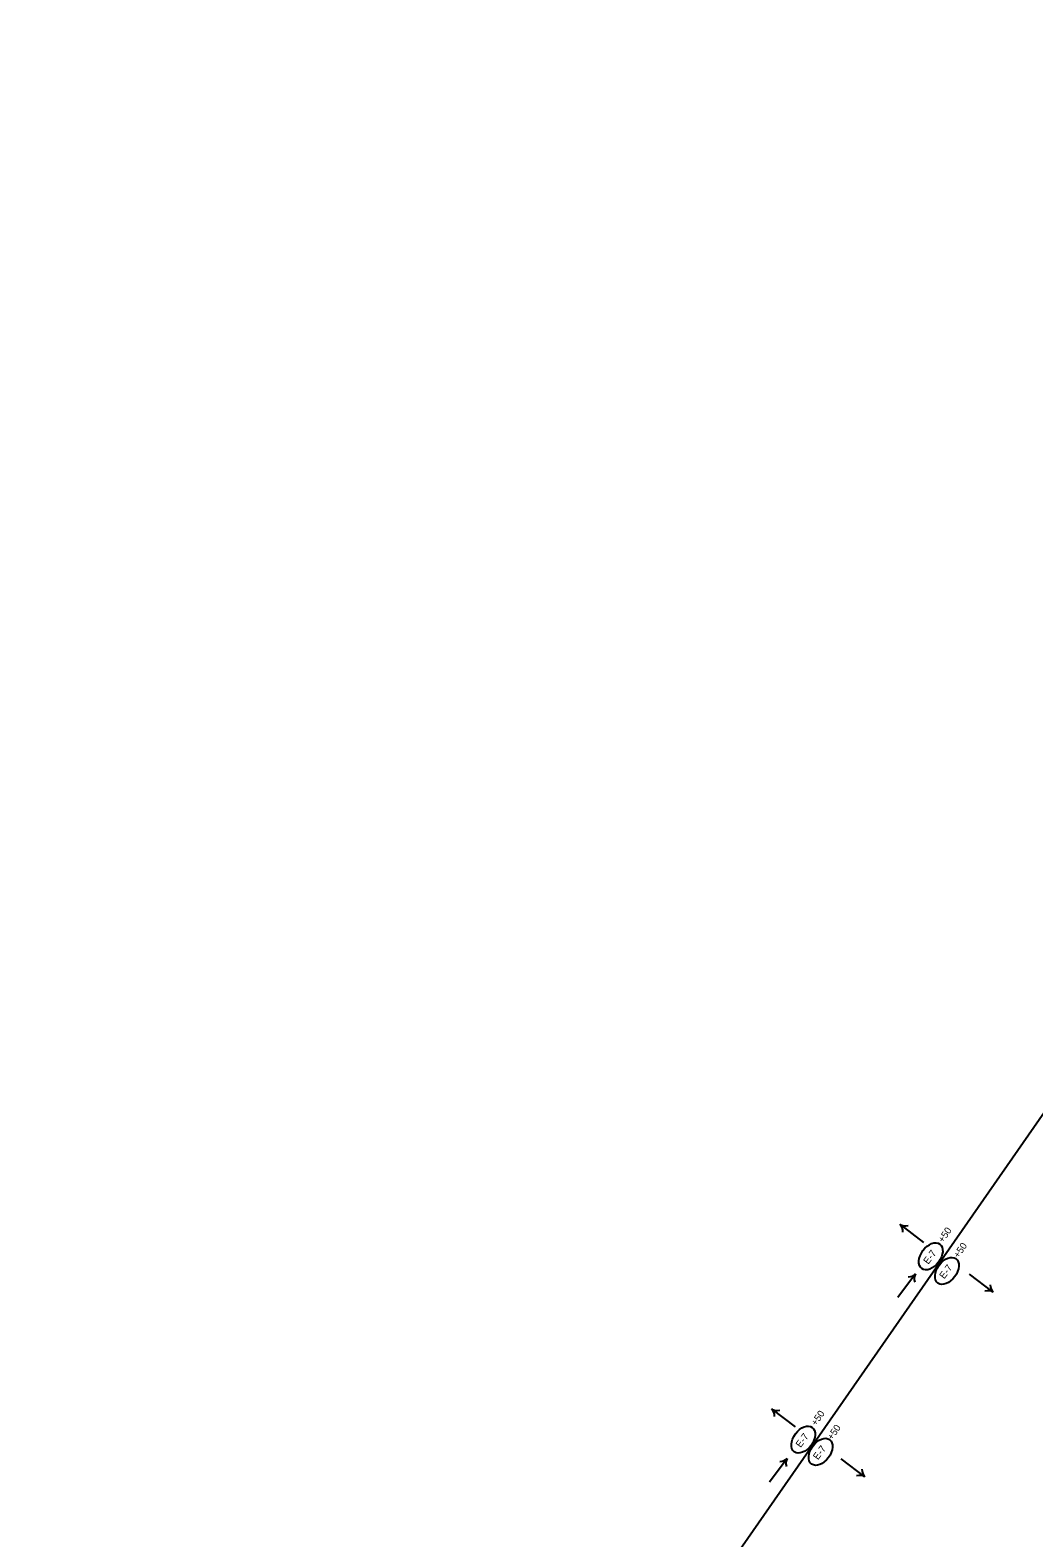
# Model space of a CAD drawing. Extents: x 669236 to 673912, y 735758 to 754788.
# Drawn here: x 671572 to 672475, y 746819 to 748174 of the extents above; entities that cross this region are included whole.
import ezdxf

# ---------------------------------------------------------------- set-up
doc = ezdxf.new("R2010")
doc.units = 0
for name, color, linetype in [('Default', 7, 'Continuous'), ('R_Erosion_2', 7, 'Continuous'), ('R_Flow Arrows', 7, 'Continuous')]:
    doc.layers.add(name, color=color, linetype=linetype)

msp = doc.modelspace()

# ---------------------------------------------------------------- linework, layer by layer
at = {"layer": 'Default'}
msp.add_line((671572, 745891.2), (673440.9, 748577.2), dxfattribs=at)
at = {"layer": 'R_Erosion_2'}
for centre in [(672381.9, 747072.1), (672396.4, 747059), (672267.2, 746907.3), (672282.8, 746896.3)]:
    msp.add_ellipse(centre, major_axis=(8.1, 11), ratio=0.638788, dxfattribs=at)
at = {"layer": 'R_Flow Arrows'}
for p, q in [((672354.3, 747100.7), (672375.4, 747084.6)), ((672368.2, 747056.3), (672352.3, 747035)), ((672437.9, 747039.9), (672416.8, 747056)), ((672238.9, 746934.7), (672260, 746918.7)), ((672252.8, 746890.3), (672236.9, 746869.1)), ((672322.5, 746873.9), (672301.4, 746890))]:
    msp.add_line(p, q, dxfattribs=at)
for centre, major_axis, start_param, end_param in [((672341.7, 747084.9), (12.2, 16), 5.662936, 6.259934), ((672366.3, 747116.9), (-12.2, -16), 0.023252, 0.620249), ((672352.3, 747068.7), (16.1, -12.1), 5.662936, 6.259934), ((672384.5, 747044.4), (-16.1, 12.1), 0.023252, 0.620249), ((672425.9, 747023.7), (12.2, 16), 0.023252, 0.620249), ((672450.5, 747055.6), (-12.2, -16), 5.662936, 6.259934), ((672226.3, 746919), (12.2, 16), 5.662936, 6.259934), ((672250.9, 746950.9), (-12.2, -16), 0.023252, 0.620249), ((672236.9, 746902.8), (16.1, -12.1), 5.662936, 6.259934), ((672269.1, 746878.5), (-16.1, 12.1), 0.023252, 0.620249), ((672335.1, 746889.7), (-12.2, -16), 5.662936, 6.259934), ((672310.5, 746857.8), (12.2, 16), 0.023252, 0.620249)]:
    msp.add_ellipse(centre, major_axis=major_axis, ratio=0.5625, start_param=start_param, end_param=end_param, dxfattribs=at)

# ---------------------------------------------------------------- texts
at = {"layer": 'R_Erosion_2'}
for s, rotation, p in [('+50', 55.5768, (672393, 747083.8)), ('+50', 55.5768, (672406.9, 747070)), ('E-7', 53.5441, (672379.6, 747064.4)), ('E-7', 53.5441, (672394, 747051.3)), ('+50', 55.5768, (672278.8, 746919.1)), ('+50', 55.5768, (672293.3, 746906.4)), ('E-7', 53.5441, (672264.8, 746899.6)), ('E-7', 53.5441, (672280.4, 746888.6))]:
    msp.add_text(s, height=6.25, rotation=rotation, dxfattribs=at).set_placement(p)

doc.saveas('drawing.dxf')
